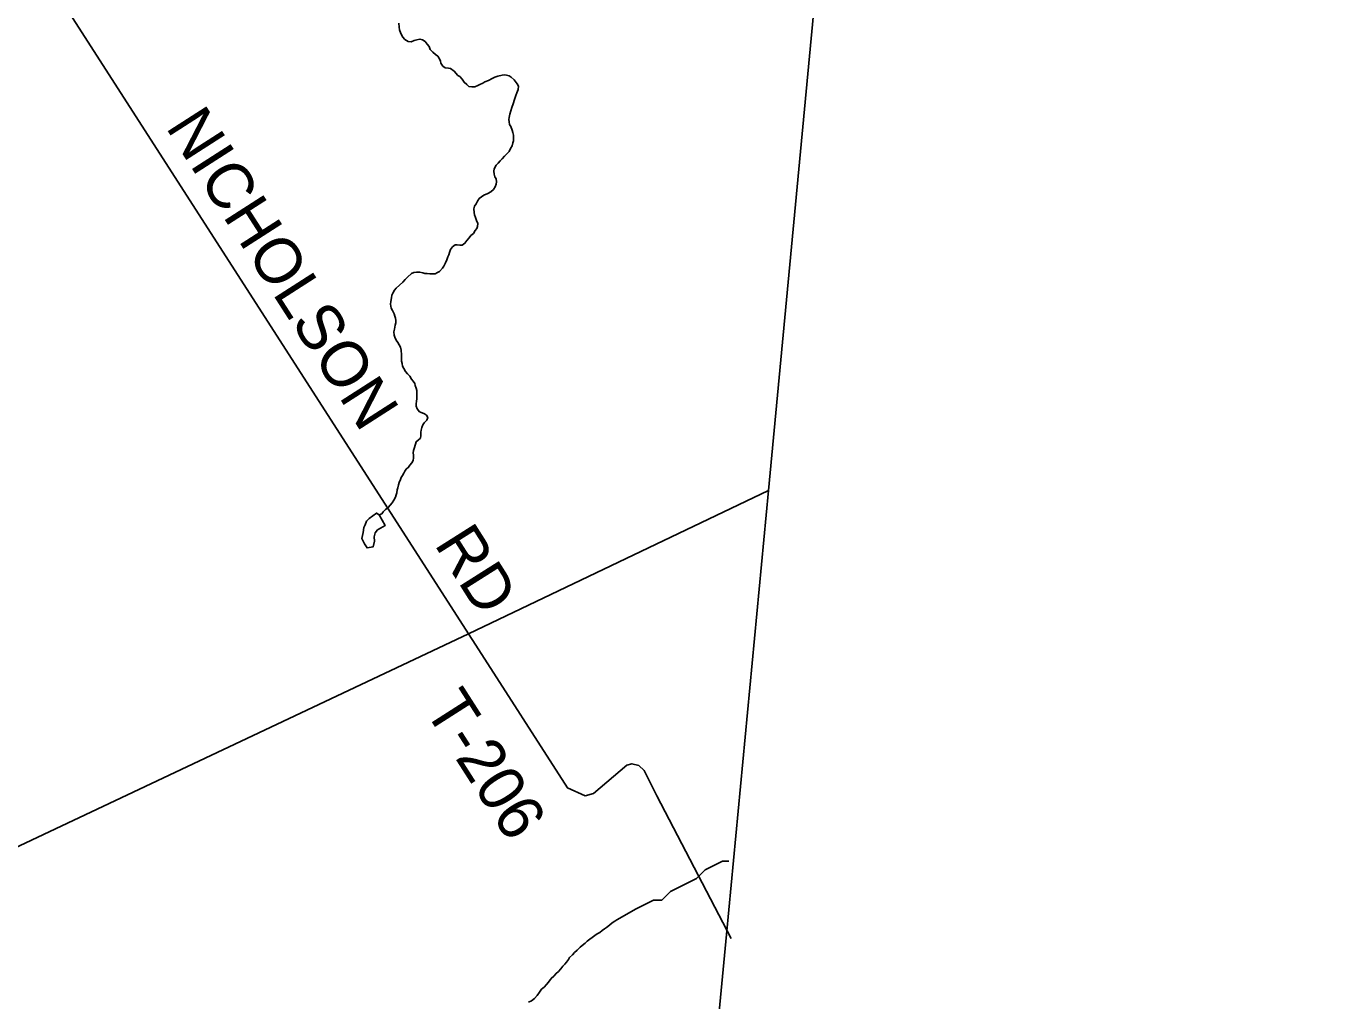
# Model space of a CAD drawing. Extents: x 1310247 to 1664935, y 284496 to 704931.
# Drawn here: x 1540499 to 1549068, y 495991 to 502367 of the extents above; entities that cross this region are included whole.
import ezdxf

# ---------------------------------------------------------------- set-up
doc = ezdxf.new("R2010")
doc.units = 0
for name, color, linetype in [('GM_X_Adjacent_County', 7, 'Continuous'), ('GM_X_Adjacent_County_Text', 7, 'Continuous'), ('GM_X_County_Subdivision_Text', 7, 'Continuous'), ('GM_X_Minor_River', 7, 'Continuous'), ('GM_X_Minor_River_Text', 7, 'Continuous'), ('GM_X_Township', 7, 'Continuous'), ('GM_X_Township_Subdivision', 7, 'Continuous')]:
    doc.layers.add(name, color=color, linetype=linetype)

msp = doc.modelspace()

# ---------------------------------------------------------------- linework, layer by layer
at = {"layer": 'GM_X_Adjacent_County'}
for points in [[(1546686.4, 513989.1), (1546297.7, 509605.7), (1545822.1, 504298.4), (1545798, 504043.7), (1545352.6, 499330.6), (1543391.6, 498392.7), (1539239.6, 496432), (1537601.9, 499058.4), (1537044, 499954.2), (1536077.6, 501508.1), (1535875.9, 501832.4), (1535555.7, 502352.1), (1532125.8, 502432.2), (1530754.3, 502475.8), (1526460.8, 502612), (1526364.4, 502615.1), (1523999.8, 502690.1), (1523132.5, 502717.6), (1519529.8, 502831.9)], [(1539239.6, 496432), (1543391.6, 498392.7), (1545352.6, 499330.6), (1545078, 496425), (1545013, 495737.5), (1545002.2, 495623.2), (1544428.8, 489554.2), (1544211.7, 487255.6), (1544122.7, 486001.5), (1543861.4, 483361.9), (1543818, 482923.1), (1543135.8, 476031.3)]]:
    msp.add_lwpolyline(points, dxfattribs=at)
at = {"layer": 'GM_X_Adjacent_County_Text'}
msp.add_lwpolyline([(1543135.8, 476031.3), (1543818, 482923.1), (1543861.4, 483361.9), (1544122.7, 486001.5), (1544211.7, 487255.6), (1544428.8, 489554.2), (1545002.2, 495623.2), (1545013, 495737.5), (1545078, 496425), (1545352.6, 499330.6), (1545798, 504043.7), (1545822.1, 504298.4), (1546297.7, 509605.7), (1546686.4, 513989.1), (1546925.5, 516687), (1547324.3, 521188.2), (1547463.3, 522758.3), (1547776.9, 526306), (1548052.5, 529426.3), (1548058.9, 529499.7), (1548609.4, 535719), (1548703.3, 536778.9), (1549067.9, 540794.2)], dxfattribs=at)
at = {"layer": 'GM_X_County_Subdivision_Text'}
for points in [[(1543440, 498317.1), (1543391.6, 498392.6), (1540375.6, 503089.9)], [(1544812, 496968), (1544621.7, 497332.3), (1544539, 497496.7), (1544505.3, 497529.4), (1544459.3, 497542.1), (1544427.1, 497532.6), (1544207.2, 497347.5), (1544154.8, 497332.2), (1544039.1, 497384.2), (1543440, 498317.1)], [(1545109.2, 496398.9), (1544812, 496968)]]:
    msp.add_lwpolyline(points, dxfattribs=at)
at = {"layer": 'GM_X_Minor_River'}
for points in [[(1542706, 499087.2), (1542703.3, 499055.2), (1542694.5, 499015.2), (1542711.9, 498980.7), (1542727.6, 498954.3), (1542768, 498961.5), (1542776.8, 498997.5), (1542773.3, 499025.7), (1542779.9, 499051.7), (1542796.4, 499071.4), (1542814.8, 499083.1), (1542845.4, 499100.6), (1542806.4, 499169.6)], [(1542806.4, 499169.6), (1542788.5, 499182), (1542741.4, 499146.8), (1542725, 499129), (1542716.4, 499105.1), (1542706, 499087.2)]]:
    msp.add_lwpolyline(points, dxfattribs=at)
at = {"layer": 'GM_X_Minor_River_Text'}
for points in [[(1542935.8, 502386.2), (1542937.2, 502360.1), (1542940.8, 502344), (1542948.2, 502319.7), (1542961.7, 502295.3), (1542975.4, 502280.9), (1542997.1, 502266.4), (1543017.2, 502265.9), (1543035.5, 502273.5), (1543053.7, 502279), (1543073.8, 502282.6), (1543089.8, 502278.2), (1543107.6, 502267.7), (1543121.2, 502249.3), (1543132.9, 502235), (1543140.5, 502214.8), (1543158.1, 502198.3), (1543175.8, 502181.8), (1543189.6, 502171.4), (1543201.2, 502153.1), (1543206.9, 502138.9), (1543210.5, 502124.8), (1543224.1, 502106.4), (1543237.9, 502096), (1543260, 502093.5), (1543274, 502091.1), (1543297.6, 502072.5), (1543321, 502045.9), (1543334.9, 502037.5), (1543350.6, 502021.1), (1543362.1, 502000.7), (1543379.8, 501986.3), (1543393.6, 501973.9), (1543413.6, 501971.4), (1543431.7, 501971), (1543451.9, 501978.5), (1543466.2, 501986.2), (1543484.5, 501995.8), (1543498.8, 502003.5), (1543521.1, 502013), (1543545.5, 502024.4), (1543563.8, 502034), (1543582, 502039.6), (1543610.3, 502046.9), (1543624.4, 502048.6), (1543640.5, 502046.2), (1543656.4, 502041.8), (1543670.3, 502033.4), (1543689.9, 502016.9), (1543709.4, 501990.4), (1543719, 501974.1), (1543716.5, 501954.1), (1543707.9, 501932.2), (1543699.4, 501914.4), (1543692.8, 501888.4), (1543684, 501858.6), (1543675.3, 501834.7), (1543668.8, 501812.8), (1543662.2, 501792.9), (1543657.7, 501770.9), (1543655.3, 501756.9), (1543657, 501742.8), (1543658.5, 501724.8), (1543668.2, 501710.5), (1543675.6, 501686.2), (1543681.3, 501672), (1543684.9, 501653.9), (1543686.3, 501631.8), (1543686, 501617.8), (1543681.6, 501603.8), (1543677.1, 501583.9), (1543666.6, 501568.1), (1543656.1, 501548.3), (1543639.6, 501530.6), (1543627.2, 501516.9), (1543610.7, 501499.2), (1543598.3, 501485.5), (1543583.9, 501471.8), (1543571.5, 501458), (1543558.8, 501434.2), (1543556.4, 501418.2)], [(1543556.4, 501418.2), (1543558, 501400.1), (1543563.5, 501382), (1543571.2, 501367.7), (1543574.8, 501349.6), (1543572.4, 501333.6), (1543565.9, 501315.7), (1543555.5, 501299.9), (1543537, 501284.3), (1543516.6, 501272.8), (1543492.2, 501261.3), (1543475.9, 501251.7), (1543461.6, 501240), (1543449.1, 501222.2), (1543440.6, 501204.4), (1543430.2, 501190.6), (1543425.7, 501172.6), (1543427.1, 501148.5), (1543430.7, 501132.4), (1543436.4, 501116.2), (1543443.9, 501096), (1543451.4, 501075.7), (1543449, 501057.7), (1543444.6, 501043.8), (1543434.2, 501030), (1543423.7, 501012.2), (1543407.3, 500998.5), (1543394.8, 500982.8), (1543380.3, 500965.1), (1543367.8, 500947.3), (1543349.4, 500933.7), (1543335.4, 500934), (1543317.4, 500936.5), (1543303.3, 500936.8), (1543286.9, 500923.2), (1543274.4, 500905.4), (1543265.9, 500887.6), (1543261.5, 500871.6), (1543255.1, 500857.7), (1543248.6, 500837.8), (1543240.1, 500820), (1543229.5, 500798.2), (1543221.1, 500784.3), (1543202.5, 500762.7), (1543188.3, 500755), (1543174, 500747.3), (1543155.9, 500747.8), (1543137.9, 500748.2), (1543119.8, 500748.6), (1543105.7, 500749), (1543091.8, 500753.3), (1543071.8, 500757.8), (1543051.7, 500758.3), (1543033.6, 500756.8), (1543019.4, 500749.1), (1542992.7, 500725.6), (1542976.2, 500710), (1542961.7, 500692.3), (1542939.1, 500672.8), (1542918.5, 500653.2), (1542908.1, 500639.4), (1542895.6, 500621.6), (1542889.3, 500607.8), (1542886.8, 500589.8), (1542884.2, 500565.7), (1542881.8, 500549.8), (1542885.1, 500523.6), (1542894.8, 500507.3), (1542904.3, 500485), (1542909.9, 500470.8), (1542913.6, 500456.7), (1542915.3, 500442.6), (1542914.9, 500426.6), (1542912.4, 500410.6), (1542907.8, 500384.6), (1542903.4, 500368.7), (1542904.8, 500346.6), (1542908.5, 500332.4), (1542918.1, 500314.1), (1542929.7, 500297.8), (1542937.4, 500283.6), (1542947, 500267.3), (1542950.5, 500247.1), (1542953.8, 500217), (1542953.4, 500200.9), (1542952.8, 500176.9), (1542956.4, 500160.7), (1542960, 500142.6), (1542967.6, 500128.4), (1542979.2, 500108), (1542992.9, 500093.6), (1543006.6, 500077.3), (1543018.1, 500058.9), (1543029.8, 500044.6), (1543039.5, 500030.3), (1543043.2, 500016.2), (1543048.8, 500000), (1543052.4, 499983.9), (1543053.8, 499957.8), (1543053.4, 499943.7), (1543053.1, 499929.7)], [(1543053.1, 499929.7), (1543050.7, 499913.7), (1543048.2, 499895.7), (1543047.9, 499881.7), (1543055.4, 499863.4), (1543071, 499845), (1543089, 499838.5), (1543102.8, 499830.2), (1543116.7, 499821.8), (1543124.3, 499807.6), (1543117.9, 499789.7), (1543101.4, 499772), (1543093, 499758.2), (1543086.6, 499742.3), (1543082.1, 499724.3), (1543079.7, 499710.4), (1543079.2, 499690.3), (1543076.8, 499672.3), (1543062.4, 499658.6), (1543048, 499648.9), (1543043.6, 499633), (1543034.9, 499605.1), (1543030.5, 499591.2), (1543030.2, 499577.1), (1543031.8, 499561), (1543031.3, 499543), (1543028.9, 499525), (1543020.5, 499511.2), (1543008.1, 499495.4), (1542999.7, 499481.6), (1542983.3, 499469.9), (1542974.9, 499456.1), (1542968.5, 499442.2), (1542960.2, 499428.3), (1542951.8, 499414.5), (1542945.4, 499400.6), (1542936.9, 499382.8), (1542932.5, 499366.8), (1542928, 499346.9), (1542925.6, 499332.9), (1542923.2, 499314.9), (1542918.8, 499300.9), (1542914.4, 499285), (1542903.9, 499267.2), (1542891.4, 499249.4), (1542878.9, 499233.7), (1542866.5, 499217.9), (1542848.1, 499204.3), (1542833.7, 499190.6), (1542823.3, 499176.8), (1542806.4, 499169.6)], [(1544361.9, 496521.5), (1544486.5, 496593), (1544543, 496621.2), (1544599.6, 496649.5), (1544656.1, 496649.5), (1544712.6, 496706), (1544769.2, 496734.3), (1544825.7, 496762.6), (1544882.2, 496790.8), (1544938.7, 496847.4), (1544995.3, 496875.6), (1545051.8, 496903.9), (1545092.4, 496903.9)], [(1544083.3, 496307.5), (1544101.8, 496323.1), (1544120.3, 496340.8), (1544134.6, 496352.4), (1544153.1, 496368), (1544167.5, 496381.8), (1544183.9, 496393.4), (1544200.2, 496405), (1544216.6, 496418.7), (1544233, 496428.3), (1544249.3, 496438), (1544265.7, 496451.6), (1544280, 496461.3), (1544294.3, 496471), (1544312.7, 496484.6), (1544331.2, 496500.2), (1544347.6, 496511.8), (1544361.9, 496521.5)], [(1543783.8, 495981.7), (1543802.2, 495991.3), (1543822.6, 496006.9), (1543839.2, 496026.5), (1543855.8, 496048.2), (1543868.3, 496066), (1543884.7, 496079.6), (1543901.2, 496097.3), (1543913.7, 496113), (1543932.4, 496136.6), (1543948.8, 496152.3), (1543963.3, 496170), (1543979.7, 496183.6), (1543994.2, 496199.3), (1544006.7, 496217.1), (1544021.1, 496230.8), (1544031.5, 496244.6), (1544043.9, 496260.3), (1544052.3, 496274.2), (1544070.8, 496291.8), (1544083.3, 496307.5)]]:
    msp.add_lwpolyline(points, dxfattribs=at)
at = {"layer": 'GM_X_Township'}
msp.add_lwpolyline([(1549067.9, 540794.2), (1548703.3, 536778.9), (1548609.4, 535719), (1548058.9, 529499.7), (1548052.5, 529426.3), (1547776.9, 526306), (1547463.3, 522758.3), (1547324.3, 521188.2), (1546925.5, 516687), (1546686.4, 513989.1), (1546297.7, 509605.7), (1545822.1, 504298.4), (1545798, 504043.7), (1545352.6, 499330.6), (1545078, 496425), (1545013, 495737.5), (1545002.2, 495623.2), (1544428.8, 489554.2), (1544211.7, 487255.6), (1544122.7, 486001.5), (1543861.4, 483361.9), (1543818, 482923.1), (1543135.8, 476031.3)], dxfattribs=at)

# ---------------------------------------------------------------- texts
at = {"layer": 'GM_X_Township_Subdivision'}
for s, rotation, p in [('NICHOLSON', 302.69913, (1541407, 501708.3)), ('RD', 302.31985, (1543163, 498979.6)), ('T-206', 302.60092, (1543095.4, 497901.2))]:
    msp.add_text(s, height=300, rotation=rotation, dxfattribs=at).set_placement(p)

doc.saveas('drawing.dxf')
